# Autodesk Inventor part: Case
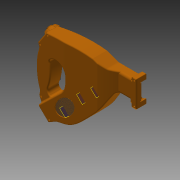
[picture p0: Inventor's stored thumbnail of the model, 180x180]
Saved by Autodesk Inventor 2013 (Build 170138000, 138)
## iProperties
Created: 2008-06
Part Number: Case
Document SubType Name: Modeling
Designer: tangg
Density: 1.06 g/cm^3
Mass: 76.5176 g
Surface Area: 2978.07 cm^2
Volume: 72.1864 cm^3
Stock Number: Case
Material: ABS Plastic
Author: tangg
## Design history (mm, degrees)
sketch "Sketch1"
  geometry: L1 (127.385, 15.24)-(71.466, 15.24); L2 (143.279, 24.13)-(143.279, -44.45); L3 (127.385, -35.56)-(92.277, -35.56); L4 (81.416, -41.677)-(60.325, -76.472); L5 (-66.363, -173.038)-(-82.55, -182.562); L6 (-82.55, -182.562)-(-114.541, -151.565); L7 (47.484, -46.179)-(34.222, -59.441) reference; L8 (47.484, -46.179)-(34.222, -59.441) reference; L9 (34.222, -59.441)-(0, -93.663); L10 (142.009, 25.4)-(133.735, 25.4); L11 (130.56, 22.225)-(130.56, 18.415); L12 (142.009, -45.72)-(133.735, -45.72); L13 (130.56, -42.545)-(130.56, -38.735); L14 (67.2, 15.978)-(37.285, 26.647); L15 (-38.763, -45.049)-(-38.763, -86.032); L16 (-76.383, -122.164)-(-38.763, -86.032); L17 (-122.604, -21.78)-(-95.903, 16.854); A1 r 3.175 centre (133.735, 22.225) between (133.735, 25.4) and (130.56, 22.225); A2 r 3.175 centre (127.385, 18.415) between (127.385, 15.24) and (130.56, 18.415); A3 r 3.175 centre (133.735, -42.545) between (130.56, -42.545) and (133.735, -45.72); A4 r 1.27 centre (142.009, 24.13) between (143.279, 24.13) and (142.009, 25.4); A5 r 1.27 centre (142.009, -44.45) between (142.009, -45.72) and (143.279, -44.45); A6 r 12.7 centre (92.277, -48.26) between (92.277, -35.56) and (81.416, -41.677); A7 r 12.7 centre (71.466, 27.94) between (67.2, 15.978) and (71.466, 15.24); A8 r 3.175 centre (127.385, -38.735) between (130.56, -38.735) and (127.385, -35.56); A9 r 29.205 centre (-63.108, -61.181) between (-38.763, -45.049) and (-81.793, -38.735); 28 further points
  constraints: 34 end point, 18 point on circle, 16 point on line, 16 tangent, 9 centre point, 4 equal radius, 2 horizontal, 40 other
  dimensions: "d25" = 3.175 radius of A1; "d26" = 1.27 radius of A4; "d27" = 12.7 radius of A6; "d137" = 15.24 distance from line of point (0, 0) L1; "d138" = 35.56 distance from line of point (0, 0) L3; "d139" = 25.4 distance from line of point (0, 0) L10; "d140" = 45.72 distance from line of point (0, 0) L12; "d141" = 3.175 radius of A8
extrude "Extrusion8" new body sketch "Sketch1" distance "d71" = 38.1; taper "d72" = 0 deg
feature "Sculpt2"
fillet "Fillet9" dims "d73" = 6.35
sketch "Sketch11"
  geometry: L1 (-127.385, 15.24)-(-71.466, 15.24) reference; L2 (-67.2, 15.978)-(-37.285, 26.647) reference; L3 (114.541, -151.565)-(82.55, -182.562) reference; L4 (82.55, -182.562)-(66.363, -173.038) reference; L5 (-60.325, -76.472)-(-81.416, -41.677) reference; L6 (-92.277, -35.56)-(-127.385, -35.56) reference; L7 (-130.56, -38.735)-(-130.56, -42.545) reference; L8 (-133.735, -45.72)-(-142.009, -45.72) reference; L9 (-143.279, -44.45)-(-143.279, 24.13) reference; L10 (-142.009, 25.4)-(-133.735, 25.4) reference; L11 (-130.56, 22.225)-(-130.56, 18.415) reference; L12 (38.763, -45.049)-(38.763, -86.032) reference; L13 (38.763, -86.032)-(76.383, -122.164) reference; L14 (95.903, 16.854)-(122.604, -21.78) reference; C1 r 2.54 at (-136.949, 19.995); C2 r 2.54 at (-136.949, -39.96); C3 r 2.54 at (92.075, 12.7); C4 r 2.54 at (115.888, -21.78); C5 r 2.54 at (112.713, -141.287); C6 r 2.54 at (80.719, -174.625); A1 r 12.7 centre (-71.466, 27.94) between (-71.466, 15.24) and (-67.2, 15.978) reference; A2 r 12.7 centre (-92.277, -48.26) between (-81.416, -41.677) and (-92.277, -35.56) reference; A3 r 3.175 centre (-133.735, -42.545) between (-133.735, -45.72) and (-130.56, -42.545) reference; A4 r 1.27 centre (-142.009, -44.45) between (-143.279, -44.45) and (-142.009, -45.72) reference; A5 r 1.27 centre (-142.009, 24.13) between (-142.009, 25.4) and (-143.279, 24.13) reference; A6 r 3.175 centre (-133.735, 22.225) between (-130.56, 22.225) and (-133.735, 25.4) reference; A7 r 3.175 centre (-127.385, 18.415) between (-130.56, 18.415) and (-127.385, 15.24) reference; A8 r 3.175 centre (-127.385, -38.735) between (-127.385, -35.56) and (-130.56, -38.735) reference; A9 r 29.205 centre (63.108, -61.181) between (81.793, -38.735) and (38.763, -45.049) reference; 5 further points
  constraints: 6 centre point, 5 equal radius, 9 other
  dimensions: "d60" = 5.08 diameter of C1
  node "Project Cut Edges3"
sketch "Sketch17"
  geometry: L1 (22.589, 40.293)-(146.914, 23.439); 1 further point
  constraints: 2 end point
extrude_surface "ExtrusionSrf4" sketch "Sketch17" dims "d49" = 406.4, "d50" = 0
workplane "Work Plane10"
feature "Sculpt6"
  workplane "Work Plane14"
  workplane "Work Plane15"
extrude "Extrusion21" cut sketch "Sketch11" stored distance "d231" = 25.4; taper "d232" = 0 deg
shell "Shell6" dims "d83" = 2.54
fillet "Fillet21" dims "d147" = 38.1
fillet "Fillet22" dims "d148" = 19.05
workplane "Work Plane17"
sketch "Sketch29" dims "d256" = 31.75, "d257" = 19.05
  geometry: L1 (-12.846, -85.936)-(71.389, -1.701) reference; 2 further points; 1 other entity
  constraints: 2 end point, 1 point on line, 5 other
extrude "Extrusion14" cut sketch "Sketch29" distance "d151" = 1.27; taper "d152" = 0 deg
sketch "Sketch30"
  geometry: L1 (-39.315, 38.1)-(-38.096, 38.1); L2 (-38.096, 38.1)-(-39.315, 38.1); 1 further point
  constraints: 4 end point
fillet "Fillet24" dims "d154" = 4.445
fillet "Fillet25" dims "d155" = 3.2385
fillet "Fillet26" dims "d156" = 3.2385
fillet "Fillet27" dims "d157" = 2
fillet "Fillet28" dims "d158" = 3.2385
fillet "Fillet29" dims "d159" = 3.2385
fillet "Fillet30" dims "d160" = 3.2385
fillet "Fillet31" dims "d161" = 44.45
sketch "Sketch31"
  geometry: L1 (0, 0)-(49.213, 60.325); L2 (49.213, 60.325)-(0, 0); L3 (0, 0)-(39.962, 25.69); L4 (39.962, 25.69)-(55.562, 25.69); L5 (37.557, 46.037)-(46.038, 56.433); L6 (63.5, 48.669)-(62.499, 25.69); L7 (62.499, 25.69)-(39.962, 25.69); L8 (36.513, 44.757)-(46.038, 56.433); L9 (47.372, 58.069)-(34.629, 42.448); L10 (34.629, 42.448)-(39.962, 25.69); L11 (47.372, 58.069)-(58.738, 44.757); L12 (58.738, 44.757)-(55.562, 25.69); 1 further point
  constraints: 24 end point, 3 point on line, 1 collinear
extrude "Extrusion15" cut sketch "Sketch31" distance "d162" = 6.35; taper "d163" = 0 deg
sketch "Sketch26"
  geometry: L1 (165.876, 8.916)-(165.876, -34.925); L2 (0.866, -13.704)-(4.374, -13.704); L3 (4.374, -13.704)-(107.022, 28.87); L4 (107.022, 28.87)-(51.873, 1.085); L5 (51.873, 1.085)-(0.866, -29.735); L6 (0.866, -29.735)-(4.374, -29.735); L7 (4.374, -29.735)-(32.002, -31.726); L8 (32.002, -31.726)-(35.304, -31.726); L9 (0, -2.54)-(55.919, -2.54) reference; L10 (35.108, -48.26)-(0, -48.26) reference; L11 (234.512, -170.453)-(202.008, -139.235) reference; L12 (163.608, -102.355)-(202.008, -139.235) reference; L13 (163.608, -59.541)-(163.608, -102.355) reference; L14 (214.402, -97.907)-(252.068, -97.907); L15 (57.716, -71.396)-(48.141, -55.6) reference; A1 r 31.745 centre (190.493, -76.421) between (206.923, -49.259) and (163.608, -59.541) reference; 33 further points; 2 other entities
  constraints: 18 end point, 2 coincident, 1 horizontal, 1 vertical, 14 other
feature "Rib9" dims "d239" = 3.81, "d240" = 2.54, "d241" = 0
sketch "Sketch54"
  geometry: L1 (-16.193, 56.878)-(15.558, 56.878) reference; L2 (-16.193, 55.291)-(-16.193, 56.878) reference; L3 (-16.193, 55.291)-(15.558, 55.291) reference; L4 (-16.193, 11.703)-(15.558, 11.703) reference; L5 (-16.193, 13.291)-(15.558, 13.291) reference; L6 (-16.193, 11.703)-(-16.193, 13.291) reference; L7 (0, 56.878)-(-16.193, 56.878); L8 (-16.193, 55.291)-(-16.193, 56.878); L9 (-16.193, 55.291)-(-13.7, 55.291); L10 (-13.7, 13.291)-(-16.193, 13.291); L11 (-16.193, 11.703)-(0, 11.703); L12 (0, 56.878)-(0, 11.703); L13 (-12.7, 54.291)-(-12.7, 14.291); L14 (-16.193, 13.291)-(-16.193, 11.703); L15 (0, 68.606)-(0, 24.765) reference; A1 r 1 centre (-13.7, 54.291) between (-12.7, 54.291) and (-13.7, 55.291); A2 r 1 centre (-13.7, 14.291) between (-13.7, 13.291) and (-12.7, 14.291); 3 further points
  constraints: 16 end point, 8 point on line, 4 point on circle, 4 tangent, 2 centre point, 1 collinear
  dimensions: "d265" = 1 radius of A1; "d266" = 12.7 distance between parallel lines of L12 L13; "d267" = 1 radius of A2
extrude "Extrusion24" cut sketch "Sketch54" distance "d268" = 5; taper "d269" = 0 deg
sketch "Sketch32"
  geometry: L1 (41.764, 44.375)-(42.438, 43.477); L2 (43.073, 41.572)-(43.073, 30.162); L3 (46.248, 26.988)-(54.955, 26.988); L4 (54.955, 26.988)-(54.955, 48.055); L5 (54.955, 48.055)-(49.72, 57.478); L6 (41.894, 48.347)-(49.72, 57.478); C1 r 1.588 at (49.212, 51.03); A1 r 3.175 centre (44.304, 46.28) between (41.894, 48.347) and (41.764, 44.375); A2 r 3.175 centre (46.248, 30.162) between (43.073, 30.162) and (46.248, 26.988); A3 r 3.175 centre (39.898, 41.572) between (43.073, 41.572) and (42.438, 43.477); 1 further point
  constraints: 12 end point, 6 point on circle, 6 tangent, 4 centre point
  dimensions: "d164" = 3.175 radius of A1; "d165" = 3.175 radius of A2; "d166" = 3.175 radius of A3
extrude "Extrusion16" join sketch "Sketch32" stored distance "d167" = 7.62; taper "d168" = 0 deg
fillet "Fillet32" dims "d169" = 1.905
shell "Shell7" dims "d170" = 0.0254
sketch "Sketch33"
  geometry: L1 (59.837, 25.958)-(82.078, 25.958); L2 (82.078, 25.958)-(82.078, -25.671); L3 (82.078, -25.671)-(59.837, -25.671); L4 (59.837, -25.671)-(59.837, 25.958); 1 further point
  constraints: 8 end point
extrude "Extrusion17" join sketch "Sketch33" stored distance "d171" = 20.32; taper "d172" = 0 deg
fillet "Fillet33" dims "d173" = 1.905
fillet "Fillet34" dims "d174" = 0.635
sketch "Sketch34"
  geometry: L1 (60.008, 54.61)-(74.93, 54.61); L2 (76.2, 53.34)-(76.2, 31.433); L3 (74.93, 30.162)-(60.008, 30.162); L4 (58.738, 31.433)-(58.738, 53.34); A1 r 1.27 centre (60.008, 53.34) between (60.008, 54.61) and (58.738, 53.34); A2 r 1.27 centre (74.93, 53.34) between (76.2, 53.34) and (74.93, 54.61); A3 r 1.27 centre (74.93, 31.433) between (74.93, 30.162) and (76.2, 31.433); A4 r 1.27 centre (60.008, 31.433) between (58.738, 31.433) and (60.008, 30.162); 5 further points
  constraints: 8 end point, 8 point on circle, 8 point on line, 8 tangent, 4 centre point, 2 equal radius
  dimensions: "d177" = 1.27 radius of A1; "d178" = 1.27 radius of A2
extrude "Extrusion18" join sketch "Sketch34" stored distance "d175" = 12.7; taper "d176" = 0 deg
fillet "Fillet35" dims "d184" = 3.175
sketch "Sketch36"
  geometry: L1 (0, 44.039)-(0, 0) reference; C1 r 3.381 at (0, 22.019); 1 further point
  constraints: 1 centre point, 1 midpoint
extrude "Extrusion20" cut sketch "Sketch36" distance "d185" = 2.54; taper "d186" = 0 deg
sketch "Sketch37"
  geometry: L1 (-111.045, -5.055)-(-107.2, 0.507) reference; L2 (-95.25, -11.861)-(-118.728, 4.365); L3 (-94.025, -10.089)-(-95.25, -11.861); L4 (-95.25, -11.861)-(-118.728, 4.365); L5 (-118.728, 4.365)-(-117.113, 6.701); L6 (-117.113, 6.701)-(-94.025, -10.089); L7 (-108.249, 0.255)-(-99.913, 12.315); L8 (-99.913, 12.315)-(-109.578, 12.47); L9 (-118.728, 4.365)-(-115.166, 9.519); L10 (-109.578, 12.47)-(-112.765, 7.86); L11 (-112.765, 7.86)-(-115.166, 9.519); 2 further points
  constraints: 20 end point, 3 parallel, 2 perpendicular, 2 point on line, 1 midpoint
revolve "Revolution1" sketch "Sketch37" stored, may be unused: angle "d187" = 90 deg
sketch "Sketch40"
  geometry: L1 (-36.223, -87.115)-(-74.624, -123.995) reference; L2 (0, -86.843)-(61.585, -25.258) reference; L3 (-82.286, -169.129)-(-38.592, -125.435) reference; L4 (53.136, -82.662)-(53.136, -82.662); L5 (28.058, -30.048)-(56.795, -58.785); L6 (-5.883, -63.99)-(22.854, -92.726); L7 (-25.456, -146.24)-(-59.397, -112.299); L8 (5.656, -113.712)-(-28.286, -79.771); 8 further points
  constraints: 14 end point, 4 parallel, 3 midpoint, 3 point on line, 2 perpendicular, 10 other
  dimensions: "d246" = 40.64 distance of L5.start L5.end; "d276" = 60 distance from line of L2.start L5; "d277" = 12 distance from line of L2.start L6; "d281" = 48 distance of L7.start L7.end; "d285" = 15 distance from line of L8 L2.start; "d286" = 45 distance from line of L8 point (-42.426, -129.27)
feature "Rib11" dims "d278" = 10, "d279" = 1, "d280" = 0
feature "Rib12" dims "d282" = 3, "d283" = 1, "d284" = 3.5 deg
workplane "Work Plane31"
sketch "Sketch56"
  geometry: C1 r 16.669 at (20.32, 0) reference; 1 further point
extrude "Extrusion26" cut sketch "Sketch56" stored distance "d288" = 12; taper "d289" = 0 deg
workplane "Work Plane30"
sketch "Sketch57"
  geometry: C1 r 16.669 at (20.32, 0) reference; 1 further point
extrude "Extrusion27" cut sketch "Sketch57" stored distance "d291" = 12; taper "d292" = 0 deg
workplane "Work Plane29"
sketch "Sketch58"
  geometry: C1 r 18.503 at (22.998, 0) reference; 1 further point
extrude "Extrusion28" cut sketch "Sketch58" stored distance "d295" = 8; taper "d296" = 0 deg
workplane "Work Plane28"
sketch "Sketch59"
  geometry: C1 r 18.503 at (24, 0) reference; 1 further point
extrude "Extrusion29" cut sketch "Sketch59" stored distance "d298" = 8; taper "d299" = 0 deg
workplane "Work Plane22"
workplane "Work Plane6"
fillet "Fillet36" dims "d205" = 3.175
fillet "Fillet37" dims "d206" = 3.175
sketch "Sketch38"
  geometry: L1 (-109.578, 12.47)-(-99.913, 12.315) reference; L2 (-100.571, 13.095)-(-108.664, 13.225); L3 (-99.913, 12.315)-(-100.571, 13.095); L4 (-108.664, 13.225)-(-109.578, 12.47); 1 further point
  constraints: 6 end point, 1 parallel
revolve "Revolution2" sketch "Sketch38" stored, may be unused: angle "d188" = 90 deg
pattern_circular "Circular Pattern1" dims angle "d190" = 360 deg
sketch "Sketch45"
  geometry: L1 (-0.158, -0.036)-(-10.293, -2.349) reference; L2 (-9.994, -3.661)-(-10.593, -1.038); L3 (-10.593, -1.038)-(-7.562, -0.346); L4 (-7.562, -0.346)-(-6.963, -2.969); L5 (-6.963, -2.969)-(-9.994, -3.661); 2 further points
  constraints: 2 end point, 1 midpoint, 1 parallel, 3 other
  dimensions: "d210" = 3.10847 distance of L2.end L3.end; "d211" = 2.69065 distance of L2.start L2.end
emboss "Emboss2" sketch "Sketch45" dims "d60" = 5.08, "d212" = 0.254, "d213" = 0
sketch "Sketch46"
  geometry: L1 (-9.28, 7.401)-(0, 0) reference; L2 (-9.118, 5.809)-(-7.692, 7.597); L3 (-7.692, 7.597)-(-5.259, 5.656); L4 (-5.259, 5.656)-(-6.685, 3.868); L5 (-6.685, 3.868)-(-9.118, 5.809); 2 further points
  constraints: 2 end point, 1 midpoint, 1 parallel, 1 point on line, 3 other
  dimensions: "d215" = 3.11222 distance of L2.end L3.end; "d216" = 2.28723 distance of L2.start L2.end
emboss "Emboss3" sketch "Sketch46" dims "d60" = 5.08, "d217" = 0.254, "d218" = 0
sketch "Sketch47"
  geometry: L1 (0, 11.87)-(0, 0) reference; L2 (-1.144, 10.764)-(1.144, 10.764); L3 (1.144, 10.764)-(1.144, 7.587); L4 (1.144, 7.587)-(-1.144, 7.587); L5 (-1.144, 7.587)-(-1.144, 10.764); 2 further points
  constraints: 2 end point, 1 midpoint, 1 parallel, 1 point on line, 1 vertical, 2 other
  dimensions: "d219" = 3.17644 distance of L2.end L3.end; "d220" = 2.28723 distance of L2.start L2.end
emboss "Emboss4" sketch "Sketch47" dims "d60" = 5.08, "d221" = 0.254, "d222" = 0
sketch "Sketch48"
  geometry: L1 (9.28, 7.401)-(0, 0) reference; L2 (7.652, 7.565)-(9.078, 5.777); L3 (9.078, 5.777)-(6.695, 3.877); L4 (6.695, 3.877)-(5.269, 5.665); L5 (5.269, 5.665)-(7.652, 7.565); 2 further points
  constraints: 2 end point, 1 midpoint, 1 parallel, 1 point on line, 3 other
  dimensions: "d223" = 3.048 distance of L2.end L3.end; "d224" = 2.28723 distance of L3.end L4.end
emboss "Emboss5" sketch "Sketch48" dims "d60" = 5.08, "d225" = 0.254, "d226" = 0
sketch "Sketch49"
  geometry: L1 (11.572, -2.641)-(1.409, -0.322); L2 (10.47, -1.217)-(9.962, -3.447); L3 (9.962, -3.447)-(6.927, -2.754); L4 (6.927, -2.754)-(7.436, -0.524); L5 (7.436, -0.524)-(10.47, -1.217); L6 (11.572, -2.641)-(0, 0) reference; 2 further points
  constraints: 4 end point, 2 parallel, 1 midpoint, 1 point on line, 3 other
  dimensions: "d227" = 3.11222 distance of L2.end L3.end; "d228" = 2.28723 distance of L3.end L4.end
emboss "Emboss6" sketch "Sketch49" dims "d60" = 5.08, "d229" = 0.254, "d230" = 0
sketch "Sketch50"
  geometry: 1 further point
sketch "Sketch51"
  geometry: 1 further point
fillet "Fillet39" dims "d259" = 0.3175
sketch "Sketch55"
  geometry: L1 (12.7, 6.985)-(25.4, 6.985) reference; L2 (25.4, 6.985)-(25.4, 19.685) reference; L3 (-12.7, 6.985)-(12.7, 6.985) reference; L4 (25.4, 19.685)-(12.7, 19.685) reference; L5 (0, 6.985)-(25.4, 6.985); L6 (25.4, 19.685)-(12.7, 19.685); L7 (12.7, 19.685)-(12.7, 26.575); L8 (10.7, 28.575)-(0, 28.575); L9 (0, 28.575)-(0, 6.985); A1 r 2 centre (10.7, 26.575) between (12.7, 26.575) and (10.7, 28.575)
  constraints: 11 end point, 2 point on circle, 2 tangent, 1 centre point, 1 midpoint
  dimensions: "d275" = 2 radius of A1
extrude "Extrusion25" cut sketch "Sketch55" distance "d272" = 5; taper "d273" = 0 deg
body "Solid1"
sketch "Sketch13"
  geometry: L1 (-125.797, 22.007)-(-90.487, 22.007); L2 (-125.797, 22.007)-(-127.827, 26.574); L3 (-127.385, 0)-(-93.42, 0) reference; L4 (-127.827, 26.574)-(-152.402, 26.574); 5 further points
  constraints: 6 end point, 2 horizontal, 3 other
body "Srf1"
body "Srf2"
node "Reference4"
node "Reference5"
node "Reference6"
node "Reference7"
node "Reference8"
node "Reference9"
node "Reference10"
node "Reference11"
node "Reference12"
node "Reference13"
node "Reference18"
node "Reference19"
extrude_surface "ExtrusionSrf3" dims "d39" = 304.8, "d40" = 0
other parameters: "d16" = 38.1, "d75" = 0, "d76" = 0, "d119" = 38.1
